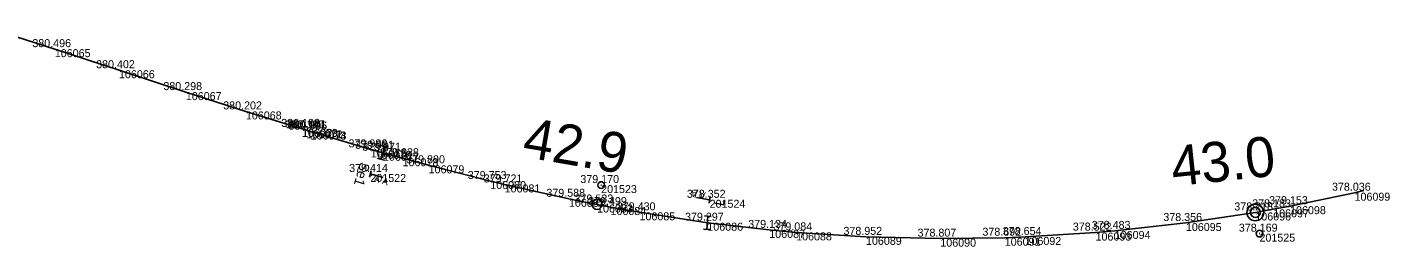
# Model space of a CAD drawing. Extents: x -514522 to -512811, y -1144589 to -1143575.
# Drawn here: x -513015.5 to -512811.3, y -1143638.6 to -1143605.7 of the extents above; entities that cross this region are included whole.
import ezdxf

# ---------------------------------------------------------------- set-up
doc = ezdxf.new("R2010")
doc.units = 0
for name, color, linetype in [('Vrstva 1', 7, 'Continuous'), ('Vrstva 3', 7, 'Continuous'), ('Vrstva 4', 7, 'Continuous'), ('Vrstva 6', 7, 'Continuous'), ('Vrstva 60', 7, 'Continuous'), ('Vrstva 61', 7, 'Continuous'), ('Vrstva 7', 7, 'Continuous')]:
    doc.layers.add(name, color=color, linetype=linetype)

msp = doc.modelspace()

# ---------------------------------------------------------------- linework, layer by layer
at = {"layer": 'Vrstva 1'}
for p, q in [((-513021.63, -1143605.71), (-513011.36, -1143609)), ((-513011.36, -1143609), (-513001.74, -1143612.16)), ((-513001.74, -1143612.16), (-512991.72, -1143615.44)), ((-512991.72, -1143615.44), (-512982.72, -1143618.34)), ((-512982.72, -1143618.34), (-512974.31, -1143620.96)), ((-512974.31, -1143620.96), (-512973.63, -1143621.17)), ((-512973.63, -1143621.17), (-512973.01, -1143621.36)), ((-512973.01, -1143621.36), (-512964, -1143624.03)), ((-512964, -1143624.03), (-512963.25, -1143624.24)), ((-512963.25, -1143624.24), (-512962.18, -1143624.54)), ((-512962.18, -1143624.54), (-512959.23, -1143625.36)), ((-512959.23, -1143625.36), (-512955.33, -1143626.42)), ((-512955.33, -1143626.42), (-512946.08, -1143628.78)), ((-512946.08, -1143628.78), (-512943.94, -1143629.29)), ((-512943.94, -1143629.29), (-512934.3, -1143631.44)), ((-512826.2, -1143632.55), (-512816.54, -1143630.53)), ((-512816.54, -1143630.53), (-512815.16, -1143630.19)), ((-512934.3, -1143631.44), (-512930.08, -1143632.29)), ((-512930.08, -1143632.29), (-512928.07, -1143632.68)), ((-512928.07, -1143632.68), (-512923.72, -1143633.47)), ((-512831.41, -1143633.49), (-512828.73, -1143633.02)), ((-512828.73, -1143633.02), (-512826.2, -1143632.55)), ((-512923.72, -1143633.47), (-512913.55, -1143635.03)), ((-512913.55, -1143635.03), (-512904.27, -1143636.11)), ((-512852.48, -1143636.26), (-512841.82, -1143635.07)), ((-512841.82, -1143635.07), (-512831.41, -1143633.49)), ((-512904.27, -1143636.11), (-512900.24, -1143636.48)), ((-512900.24, -1143636.48), (-512889.77, -1143637.15)), ((-512889.77, -1143637.15), (-512878.63, -1143637.42)), ((-512878.63, -1143637.42), (-512868.97, -1143637.28)), ((-512868.97, -1143637.28), (-512865.86, -1143637.17)), ((-512865.86, -1143637.17), (-512855.36, -1143636.51)), ((-512855.36, -1143636.51), (-512852.48, -1143636.26))]:
    msp.add_line(p, q, dxfattribs=at)
at = {"layer": 'Vrstva 3'}
for p, q in [((-512961.92, -1143623.58), (-512962.44, -1143625.51)), ((-512962.4, -1143623.45), (-512961.44, -1143623.7)), ((-512962.92, -1143625.38), (-512961.95, -1143625.64)), ((-512913.96, -1143633.99), (-512912.96, -1143634.08)), ((-512913.46, -1143634.03), (-512913.64, -1143636.03)), ((-512914.13, -1143635.98), (-512913.14, -1143636.07))]:
    msp.add_line(p, q, dxfattribs=at)
at = {"layer": 'Vrstva 4'}
msp.add_line((-512959.23, -1143625.36), (-512955.33, -1143626.42), dxfattribs=at)
at = {"layer": 'Vrstva 6'}
for p, q in [((-512963.93, -1143627.24), (-512964.19, -1143628.2)), ((-512962.15, -1143628.23), (-512964.06, -1143627.72)), ((-512915.16, -1143631.25), (-512913.21, -1143631.59)), ((-512913.29, -1143632.08), (-512913.12, -1143631.1))]:
    msp.add_line(p, q, dxfattribs=at)
at = {"layer": 'Vrstva 60'}
for p, q in [((-513011.36, -1143609), (-513011.36, -1143609)), ((-513001.74, -1143612.16), (-513001.74, -1143612.16)), ((-512991.72, -1143615.44), (-512991.72, -1143615.44)), ((-512982.72, -1143618.34), (-512982.72, -1143618.34)), ((-512974.31, -1143620.96), (-512974.31, -1143620.96)), ((-512974.28, -1143620.97), (-512974.28, -1143620.97)), ((-512973.63, -1143621.17), (-512973.63, -1143621.17)), ((-512973.61, -1143621.18), (-512973.61, -1143621.18)), ((-512973.01, -1143621.36), (-512973.01, -1143621.36)), ((-512973.01, -1143621.36), (-512973.01, -1143621.36)), ((-512964, -1143624.03), (-512964, -1143624.03)), ((-512963.25, -1143624.24), (-512963.25, -1143624.24)), ((-512962.18, -1143624.54), (-512962.18, -1143624.54)), ((-512959.23, -1143625.36), (-512959.23, -1143625.36)), ((-512955.33, -1143626.42), (-512955.33, -1143626.42)), ((-512964.06, -1143627.72), (-512964.06, -1143627.72)), ((-512946.08, -1143628.78), (-512946.08, -1143628.78)), ((-512943.94, -1143629.29), (-512943.94, -1143629.29)), ((-512929.47, -1143629.38), (-512929.47, -1143629.38)), ((-512816.54, -1143630.53), (-512816.54, -1143630.53)), ((-512934.3, -1143631.44), (-512934.3, -1143631.44)), ((-512930.08, -1143632.29), (-512930.08, -1143632.29)), ((-512928.07, -1143632.68), (-512928.07, -1143632.68)), ((-512913.21, -1143631.59), (-512913.21, -1143631.59)), ((-512828.73, -1143633.02), (-512828.73, -1143633.02)), ((-512826.2, -1143632.55), (-512826.2, -1143632.55)), ((-512923.72, -1143633.47), (-512923.72, -1143633.47)), ((-512913.55, -1143635.03), (-512913.55, -1143635.03)), ((-512841.82, -1143635.07), (-512841.82, -1143635.07)), ((-512831.41, -1143633.49), (-512831.41, -1143633.49)), ((-512904.27, -1143636.11), (-512904.27, -1143636.11)), ((-512900.24, -1143636.48), (-512900.24, -1143636.48)), ((-512889.77, -1143637.15), (-512889.77, -1143637.15)), ((-512878.63, -1143637.42), (-512878.63, -1143637.42)), ((-512868.97, -1143637.28), (-512868.97, -1143637.28)), ((-512865.86, -1143637.17), (-512865.86, -1143637.17)), ((-512855.36, -1143636.51), (-512855.36, -1143636.51)), ((-512852.48, -1143636.26), (-512852.48, -1143636.26)), ((-512830.79, -1143636.67), (-512830.79, -1143636.67))]:
    msp.add_line(p, q, dxfattribs=at)
at = {"layer": 'Vrstva 7'}
for p, q in [((-512929.52, -1143629.38), (-512929.42, -1143629.38)), ((-512830.84, -1143636.67), (-512830.73, -1143636.67))]:
    msp.add_line(p, q, dxfattribs=at)
for centre, radius in [((-512929.47, -1143629.38), 0.5), ((-512930.08, -1143632.29), 0.75), ((-512831.41, -1143633.49), 1.25), ((-512831.41, -1143633.49), 0.752), ((-512830.79, -1143636.67), 0.5)]:
    msp.add_circle(centre, radius, dxfattribs=at)

# ---------------------------------------------------------------- texts
at = {"layer": 'Vrstva 6'}
for s, height, rotation, p in [('Se1', 1.5, 253.4684, (-512965.54, -1143625.85)), ('  A A ', 1, 345, (-512964.32, -1143628.68)), ('  A A ', 1, 170, (-512913.03, -1143630.6)), ('L', 1.5, 78.4684, (-512911.11, -1143632.61))]:
    msp.add_text(s, height=height, rotation=rotation, dxfattribs=at).set_placement(p)
at = {"layer": 'Vrstva 60'}
for s, p in [('106065', (-513011.36, -1143610.2)), ('106066', (-513001.74, -1143613.36)), ('106067', (-512991.72, -1143616.64)), ('106068', (-512982.72, -1143619.54)), ('106069', (-512974.31, -1143622.16)), ('106070', (-512974.28, -1143622.17)), ('106071', (-512973.63, -1143622.37)), ('106072', (-512973.61, -1143622.38)), ('106073', (-512973.01, -1143622.56)), ('106074', (-512973.01, -1143622.56)), ('106075', (-512964, -1143625.23)), ('106076', (-512963.25, -1143625.44)), ('106077', (-512962.18, -1143625.74)), ('106078', (-512959.23, -1143626.56)), ('106079', (-512955.33, -1143627.62)), ('201522', (-512964.06, -1143628.92)), ('106080', (-512946.08, -1143629.98)), ('106081', (-512943.94, -1143630.49)), ('201523', (-512929.47, -1143630.58)), ('106099', (-512816.54, -1143631.73)), ('106082', (-512934.3, -1143632.64)), ('106083', (-512930.08, -1143633.5)), ('106084', (-512928.07, -1143633.88)), ('201524', (-512913.21, -1143632.79)), ('106097', (-512828.73, -1143634.22)), ('106098', (-512826.2, -1143633.75)), ('106085', (-512923.72, -1143634.67)), ('106086', (-512913.55, -1143636.23)), ('106095', (-512841.82, -1143636.27)), ('106096', (-512831.41, -1143634.69)), ('106087', (-512904.27, -1143637.31)), ('106088', (-512900.24, -1143637.68)), ('106089', (-512889.77, -1143638.35)), ('106090', (-512878.63, -1143638.62)), ('106091', (-512868.97, -1143638.48)), ('106092', (-512865.86, -1143638.37)), ('106093', (-512855.36, -1143637.71)), ('106094', (-512852.48, -1143637.46)), ('201525', (-512830.79, -1143637.87))]:
    msp.add_text(s, height=1.2, dxfattribs=at).set_placement(p)
at = {"layer": 'Vrstva 61'}
for s, p in [('380.496', (-513014.73, -1143608.7)), ('380.402', (-513005.17, -1143611.86)), ('380.298', (-512995.09, -1143615.14)), ('380.202', (-512986.12, -1143618.04)), ('380.106', (-512977.42, -1143620.66)), ('380.108', (-512977.41, -1143620.67)), ('380.100', (-512976.76, -1143620.87)), ('380.101', (-512976.48, -1143620.88)), ('380.095', (-512976.37, -1143621.06)), ('380.096', (-512976.34, -1143621.06)), ('379.986', (-512967.33, -1143623.73)), ('379.981', (-512966.34, -1143623.94)), ('379.971', (-512965.28, -1143624.24)), ('379.938', (-512962.59, -1143625.06)), ('379.890', (-512958.68, -1143626.12)), ('379.414', (-512967.24, -1143627.42)), ('379.753', (-512949.46, -1143628.48)), ('379.721', (-512947.07, -1143628.99)), ('379.170', (-512932.59, -1143629.08)), ('378.036', (-512819.92, -1143630.23)), ('379.588', (-512937.68, -1143631.14)), ('379.533', (-512933.46, -1143632)), ('379.499', (-512931.42, -1143632.38)), ('378.352', (-512916.62, -1143631.29)), ('378.153', (-512829.35, -1143632.25)), ('379.430', (-512927.12, -1143633.17)), ('378.218', (-512834.56, -1143633.19)), ('378.183', (-512831.88, -1143632.72)), ('379.297', (-512916.9, -1143634.73)), ('379.134', (-512907.42, -1143635.81)), ('379.084', (-512903.64, -1143636.18)), ('378.522', (-512858.77, -1143636.21)), ('378.483', (-512855.92, -1143635.96)), ('378.356', (-512845.2, -1143634.77)), ('378.169', (-512833.88, -1143636.37)), ('378.952', (-512893.15, -1143636.85)), ('378.807', (-512882.04, -1143637.12)), ('378.692', (-512872.32, -1143636.98)), ('378.654', (-512869.27, -1143636.87))]:
    msp.add_text(s, height=1.2, dxfattribs=at).set_placement(p)
at = {"layer": 'Vrstva 7'}
for s, rotation, p in [('42.9', 350.2944, (-512941.45, -1143625.11)), ('43.0', 6.012, (-512843.72, -1143629.58))]:
    msp.add_text(s, height=6, rotation=rotation, dxfattribs=at).set_placement(p)

doc.saveas('drawing.dxf')
